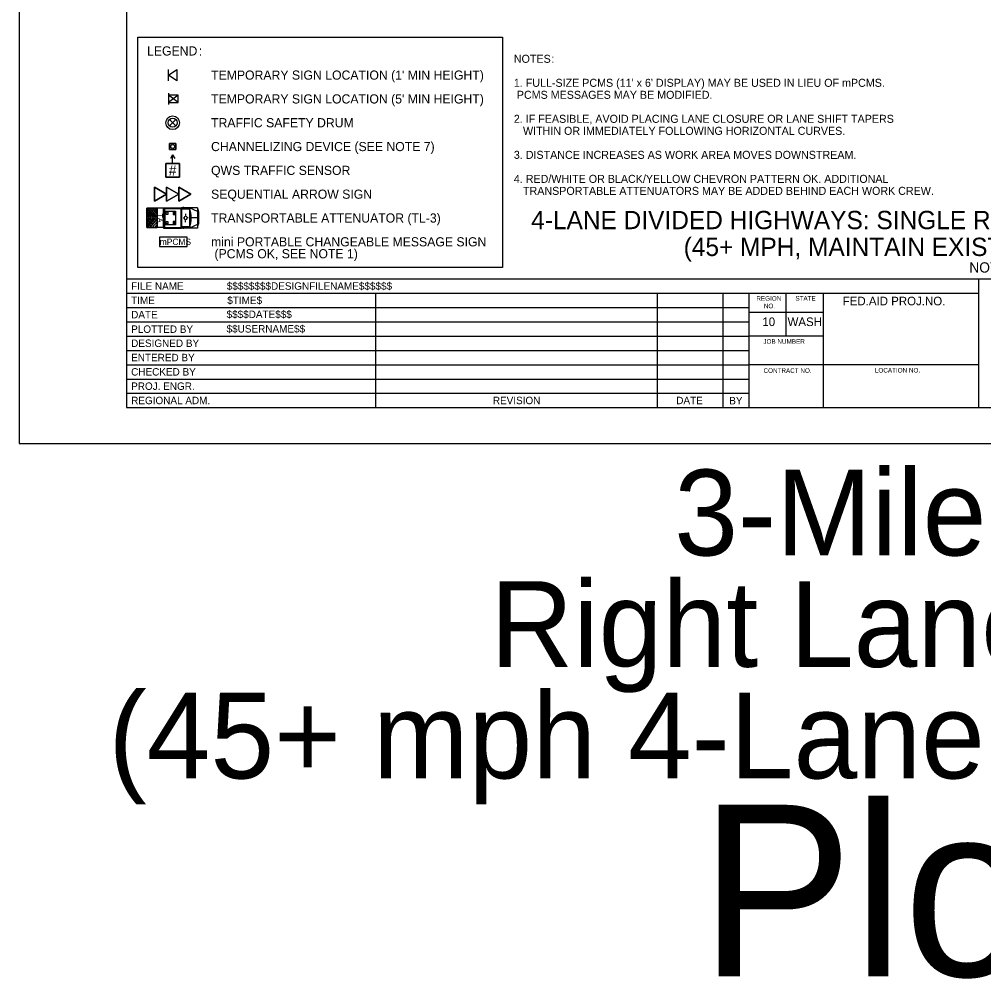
# Model space of a CAD drawing. Extents: x 99958 to 100136, y 99935 to 100013.
# Drawn here: x 100019.06 to 100027.5, y 99995.01 to 100003.4 of the extents above; entities that cross this region are included whole.
import ezdxf

# ---------------------------------------------------------------- set-up
doc = ezdxf.new("R2010")
doc.units = 0
for name, color, linetype in [('SH_DE_DetailHeading1Text', 7, 'Continuous'), ('SH_GI_GeneralNotesBodyText', 7, 'Continuous'), ('SH_GI_PlotLimits', 7, 'Continuous'), ('SH_GI_SheetBorder', 7, 'Continuous'), ('SH_GI_SheetLocationText', 7, 'Continuous'), ('SH_GI_SheetTextInCells', 7, 'Continuous'), ('SH_GI_TitleBlockText', 7, 'Continuous'), ('TR_WZ_PCMS', 7, 'Continuous'), ('TR_WZ_PortableSignMount5ftMinBlk-Wht', 7, 'Continuous'), ('TR_WZ_PortableSignMountBlk-Wht', 7, 'Continuous'), ('TR_WZ_SequentialArrowSign', 7, 'Continuous'), ('TR_WZ_TrafficCone', 7, 'Continuous'), ('TR_WZ_TrafficSafetyDrum', 7, 'Continuous'), ('TR_WZ_TransportableAttenuator', 7, 'Continuous'), ('TR_WZ_WorkZoneDetails', 7, 'Continuous'), ('TR_WZ_WorkZoneTextCurrent', 7, 'Continuous')]:
    doc.layers.add(name, color=color, linetype=linetype)

msp = doc.modelspace()

# ---------------------------------------------------------------- linework, layer by layer
at = {"layer": 'SH_GI_PlotLimits'}
msp.add_lwpolyline([(100019.0625, 99999.6875), (100036.0625, 99999.6875), (100036.0625, 100010.6875), (100019.0625, 100010.6875)], close=True, dxfattribs=at)
at = {"layer": 'SH_GI_SheetBorder'}
for p, q in [((100020, 100010.375), (100020, 100000)), ((100020, 100001.1259), (100035.75, 100001.1259)), ((100027.4566, 100000), (100027.4566, 100001.1259)), ((100020, 100001.0008), (100027.4566, 100001.0008)), ((100022.179, 100001.0008), (100022.179, 100000)), ((100024.641, 100001.0008), (100024.641, 100000)), ((100025.2164, 100001.0008), (100025.2164, 100000)), ((100025.4451, 100001.0008), (100025.4451, 100000)), ((100025.7719, 100000.6255), (100025.7719, 100001.0008)), ((100026.0956, 100000), (100026.0956, 100001.0008)), ((100020, 100000.8757), (100022.1821, 100000.8757)), ((100022.1821, 100000.8757), (100025.4466, 100000.8757)), ((100026.0958, 100000.831), (100025.4466, 100000.831)), ((100020, 100000.7506), (100022.1821, 100000.7506)), ((100022.1821, 100000.7506), (100025.4466, 100000.7506)), ((100020, 100000.6255), (100025.4466, 100000.6255)), ((100026.0958, 100000.6255), (100025.4466, 100000.6255)), ((100020, 100000.5004), (100025.4466, 100000.5004)), ((100020, 100000.3753), (100025.4466, 100000.3753)), ((100027.4566, 100000.3753), (100025.4466, 100000.3753)), ((100020, 100000.2502), (100025.4466, 100000.2502)), ((100020, 100000.1251), (100025.4466, 100000.1251)), ((100020, 100000), (100035.75, 100000))]:
    msp.add_line(p, q, dxfattribs=at)
at = {"layer": 'TR_WZ_PCMS'}
msp.add_lwpolyline([(100020.2899, 100001.41), (100020.5299, 100001.41), (100020.5299, 100001.49), (100020.2899, 100001.49)], close=True, dxfattribs=at)
msp.add_lwpolyline([(100020.2899, 100001.41), (100020.5299, 100001.41), (100020.5299, 100001.49), (100020.2899, 100001.49), (100020.2899, 100001.41)], dxfattribs=at)
at = {"layer": 'TR_WZ_PortableSignMount5ftMinBlk-Wht'}
for p, q in [((100020.3682, 100002.7497), (100020.3682, 100002.6497)), ((100020.4516, 100002.6672), (100020.3682, 100002.7322)), ((100020.4516, 100002.7322), (100020.3682, 100002.6672)), ((100020.4099, 100002.6997), (100020.4099, 100002.6997)), ((100020.41, 100002.6996), (100020.41, 100002.6996))]:
    msp.add_line(p, q, dxfattribs=at)
msp.add_lwpolyline([(100020.4516, 100002.6672), (100020.4516, 100002.7322), (100020.3682, 100002.7322), (100020.3682, 100002.6672)], close=True, dxfattribs=at)
at = {"layer": 'TR_WZ_PortableSignMountBlk-Wht'}
msp.add_line((100020.3682, 100002.858), (100020.3682, 100002.958), dxfattribs=at)
msp.add_lwpolyline([(100020.3682, 100002.9079), (100020.44, 100002.958), (100020.44, 100002.858)], close=True, dxfattribs=at)
at = {"layer": 'TR_WZ_SequentialArrowSign'}
for points in [[(100020.3508, 100001.8666), (100020.2441, 100001.8048), (100020.2441, 100001.9284), (100020.3508, 100001.8666)], [(100020.2441, 100001.9284), (100020.2441, 100001.8048), (100020.3508, 100001.8666), (100020.2441, 100001.9284)], [(100020.4575, 100001.8666), (100020.3508, 100001.8048), (100020.3508, 100001.8666), (100020.3508, 100001.9284), (100020.4575, 100001.8666)], [(100020.3508, 100001.9284), (100020.3508, 100001.8666), (100020.3508, 100001.8048), (100020.4575, 100001.8666), (100020.3508, 100001.9284)], [(100020.5641, 100001.8666), (100020.4575, 100001.8048), (100020.4575, 100001.8666), (100020.4575, 100001.9284), (100020.5641, 100001.8666)], [(100020.4575, 100001.9284), (100020.4575, 100001.8666), (100020.4575, 100001.8048), (100020.5641, 100001.8666), (100020.4575, 100001.9284)]]:
    msp.add_lwpolyline(points, dxfattribs=at)
at = {"layer": 'TR_WZ_TrafficCone'}
for points in [[(100020.4308, 100002.3098), (100020.4308, 100002.2565), (100020.3775, 100002.2565), (100020.3775, 100002.3098), (100020.4308, 100002.3098)], [(100020.3775, 100002.3098), (100020.3775, 100002.2565), (100020.4308, 100002.2565), (100020.4308, 100002.3098), (100020.3775, 100002.3098)]]:
    msp.add_lwpolyline(points, dxfattribs=at)
msp.add_circle((100020.4041, 100002.2832), 0.0167, dxfattribs=at)
at = {"layer": 'TR_WZ_TrafficSafetyDrum'}
for p, q in [((100020.4324, 100002.5197), (100020.3758, 100002.4632)), ((100020.4324, 100002.4632), (100020.3758, 100002.5197))]:
    msp.add_line(p, q, dxfattribs=at)
for radius in [0.06, 0.06, 0.04]:
    msp.add_circle((100020.4041, 100002.4914), radius, dxfattribs=at)
at = {"layer": 'TR_WZ_TransportableAttenuator'}
for p, q in [((100020.1791, 100001.7269), (100020.2355, 100001.659)), ((100020.1791, 100001.705), (100020.1791, 100001.7269)), ((100020.2355, 100001.659), (100020.1791, 100001.7269)), ((100020.1791, 100001.7269), (100020.1791, 100001.705)), ((100020.2551, 100001.6585), (100020.185, 100001.743)), ((100020.185, 100001.743), (100020.2041, 100001.743)), ((100020.185, 100001.743), (100020.2551, 100001.6585)), ((100020.2041, 100001.743), (100020.185, 100001.743)), ((100020.2041, 100001.743), (100020.2676, 100001.6659)), ((100020.2676, 100001.6659), (100020.2041, 100001.743)), ((100020.2676, 100001.6908), (100020.2248, 100001.743)), ((100020.2248, 100001.743), (100020.2439, 100001.743)), ((100020.2439, 100001.743), (100020.2248, 100001.743)), ((100020.2248, 100001.743), (100020.2676, 100001.6908)), ((100020.2439, 100001.743), (100020.2676, 100001.7144)), ((100020.2676, 100001.7144), (100020.2439, 100001.743)), ((100020.2676, 100001.574), (100020.2676, 100001.743)), ((100020.3279, 100001.743), (100020.2676, 100001.743)), ((100020.3208, 100001.7399), (100020.3208, 100001.5768)), ((100020.3241, 100001.7454), (100020.3274, 100001.7454)), ((100020.3274, 100001.7454), (100020.3274, 100001.5713)), ((100020.3279, 100001.7483), (100020.4803, 100001.7483)), ((100020.3279, 100001.7483), (100020.3279, 100001.5683)), ((100020.3279, 100001.7427), (100020.3279, 100001.574)), ((100020.3323, 100001.7411), (100020.3323, 100001.5755)), ((100020.3323, 100001.7411), (100020.476, 100001.7411)), ((100020.476, 100001.7411), (100020.476, 100001.5755)), ((100020.4803, 100001.7483), (100020.4803, 100001.5683)), ((100020.4824, 100001.7483), (100020.4824, 100001.5683)), ((100020.6223, 100001.7483), (100020.4824, 100001.7483)), ((100020.551, 100001.7344), (100020.4824, 100001.7344)), ((100020.5014, 100001.7509), (100020.493, 100001.7509)), ((100020.551, 100001.7483), (100020.5421, 100001.7344)), ((100020.551, 100001.7483), (100020.551, 100001.5683)), ((100020.5523, 100001.7483), (100020.5523, 100001.5683)), ((100020.6223, 100001.7153), (100020.5523, 100001.7483)), ((100020.6223, 100001.7483), (100020.6223, 100001.5683)), ((100020.6223, 100001.7483), (100020.6291, 100001.712)), ((100020.2174, 100001.6592), (100020.1791, 100001.705)), ((100020.1791, 100001.705), (100020.2174, 100001.6592)), ((100020.1791, 100001.6818), (100020.1987, 100001.6586)), ((100020.1791, 100001.635), (100020.1791, 100001.6818)), ((100020.1987, 100001.6586), (100020.1791, 100001.6818)), ((100020.1791, 100001.6818), (100020.1791, 100001.635)), ((100020.1791, 100001.6131), (100020.2174, 100001.6592)), ((100020.2174, 100001.6592), (100020.1791, 100001.6131)), ((100020.2355, 100001.659), (100020.1791, 100001.5911)), ((100020.1791, 100001.5911), (100020.2355, 100001.659)), ((100020.1987, 100001.6586), (100020.1791, 100001.635)), ((100020.1791, 100001.635), (100020.1987, 100001.6586)), ((100020.1849, 100001.5739), (100020.2551, 100001.6585)), ((100020.2551, 100001.6585), (100020.1849, 100001.5739)), ((100020.2676, 100001.6509), (100020.2037, 100001.5739)), ((100020.2037, 100001.5739), (100020.2676, 100001.6509)), ((100020.2676, 100001.7144), (100020.2676, 100001.6908)), ((100020.2676, 100001.6908), (100020.2676, 100001.7144)), ((100020.2676, 100001.6659), (100020.2676, 100001.6509)), ((100020.2676, 100001.6509), (100020.2676, 100001.6659)), ((100020.3208, 100001.671), (100020.3274, 100001.6676)), ((100020.3208, 100001.6456), (100020.3274, 100001.649)), ((100020.3226, 100001.6583), (100020.3257, 100001.6583)), ((100020.3241, 100001.6608), (100020.3241, 100001.6558)), ((100020.4951, 100001.6584), (100020.5045, 100001.6584)), ((100020.507, 100001.658), (100020.507, 100001.658)), ((100020.5175, 100001.694), (100020.5175, 100001.6794)), ((100020.5175, 100001.6226), (100020.5175, 100001.6372)), ((100020.5398, 100001.6584), (100020.5305, 100001.6584)), ((100020.6223, 100001.6583), (100020.566, 100001.6583)), ((100020.6291, 100001.712), (100020.6291, 100001.6047)), ((100020.1791, 100001.5911), (100020.1791, 100001.6131)), ((100020.1791, 100001.6131), (100020.1791, 100001.5911)), ((100020.2037, 100001.5739), (100020.1849, 100001.5739)), ((100020.1849, 100001.5739), (100020.2037, 100001.5739)), ((100020.2243, 100001.5739), (100020.2676, 100001.626)), ((100020.2676, 100001.626), (100020.2243, 100001.5739)), ((100020.2446, 100001.5739), (100020.2243, 100001.5739)), ((100020.2243, 100001.5739), (100020.2446, 100001.5739)), ((100020.2676, 100001.6011), (100020.2446, 100001.5739)), ((100020.2446, 100001.5739), (100020.2676, 100001.6011)), ((100020.2676, 100001.626), (100020.2676, 100001.6011)), ((100020.2676, 100001.6011), (100020.2676, 100001.626)), ((100020.3279, 100001.574), (100020.2676, 100001.574)), ((100020.3241, 100001.5713), (100020.3274, 100001.5713)), ((100020.3279, 100001.5683), (100020.4803, 100001.5683)), ((100020.3323, 100001.5755), (100020.476, 100001.5755)), ((100020.551, 100001.5823), (100020.4824, 100001.5823)), ((100020.6223, 100001.5683), (100020.4824, 100001.5683)), ((100020.5014, 100001.5658), (100020.493, 100001.5658)), ((100020.5437, 100001.5823), (100020.551, 100001.5683)), ((100020.6223, 100001.6013), (100020.5523, 100001.5683)), ((100020.6223, 100001.5683), (100020.6291, 100001.6047))]:
    msp.add_line(p, q, dxfattribs=at)
for points in [[(100020.2676, 100001.5739), (100020.1791, 100001.5739), (100020.1791, 100001.743), (100020.2676, 100001.743)], [(100020.3398, 100001.7183), (100020.4298, 100001.7183), (100020.4298, 100001.5983), (100020.3398, 100001.5983)], [(100020.3473, 100001.7108), (100020.3623, 100001.7108), (100020.3623, 100001.6883), (100020.3473, 100001.6883)], [(100020.4223, 100001.7108), (100020.4073, 100001.7108), (100020.4073, 100001.6883), (100020.4223, 100001.6883)], [(100020.3473, 100001.6283), (100020.3623, 100001.6283), (100020.3623, 100001.6058), (100020.3473, 100001.6058)], [(100020.4223, 100001.6283), (100020.4073, 100001.6283), (100020.4073, 100001.6058), (100020.4223, 100001.6058)]]:
    msp.add_lwpolyline(points, close=True, dxfattribs=at)
msp.add_lwpolyline([(100020.2676, 100001.743), (100020.1791, 100001.743), (100020.1791, 100001.5739), (100020.2676, 100001.574)], dxfattribs=at)
for centre, major_axis, start_param, end_param in [((100020.3241, 100001.7399), (0, 0.00549), 6.283185, 7.853982), ((100020.4523, 100001.6583), (0, 0.1889), 4.215852, 5.209111), ((100020.3241, 100001.5768), (0, -0.00549), 4.712389, 6.283185)]:
    msp.add_ellipse(centre, major_axis=major_axis, ratio=0.60201, start_param=start_param, end_param=end_param, dxfattribs=at)
for centre, major_axis in [((100020.3241, 100001.6583), (0, -0.00254)), ((100020.5175, 100001.6583), (0, -0.0173))]:
    msp.add_ellipse(centre, major_axis=major_axis, ratio=0.60201, dxfattribs=at)
at = {"layer": 'TR_WZ_WorkZoneDetails'}
for p, q in [((100020.4041, 100002.2099), (100020.3854, 100002.1774)), ((100020.4041, 100002.1349), (100020.4041, 100002.2099)), ((100020.4041, 100002.2099), (100020.4229, 100002.1774))]:
    msp.add_line(p, q, dxfattribs=at)
msp.add_lwpolyline([(100020.3441, 100002.1349), (100020.4641, 100002.1349), (100020.4641, 100002.0149), (100020.3441, 100002.0149)], close=True, dxfattribs=at)
msp.add_lwpolyline([(100020.3441, 100002.1349), (100020.3441, 100002.0149), (100020.4641, 100002.0149), (100020.4641, 100002.1349), (100020.4041, 100002.1349), (100020.3441, 100002.1349)], dxfattribs=at)
at = {"layer": 'TR_WZ_WorkZoneTextCurrent'}
msp.add_lwpolyline([(100020.1, 100003.2393), (100023.2886, 100003.2393), (100023.2886, 100001.2259), (100020.1, 100001.2259)], close=True, dxfattribs=at)

# ---------------------------------------------------------------- texts
at = {"layer": 'SH_DE_DetailHeading1Text'}
for s, height, p in [('4-LANE DIVIDED HIGHWAYS: SINGLE RIGHT LANE CLOSURE + 3-MILE QWS', 0.16, (100023.5403, 100001.5606)), ('(45+ MPH, MAINTAIN EXISTING SPEED LIMIT)', 0.16, (100024.8739, 100001.3259)), ('NOT TO SCALE', 0.09, (100027.3725, 100001.1809))]:
    msp.add_text(s, height=height, rotation=360, dxfattribs=at).set_placement(p)
at = {"layer": 'SH_GI_GeneralNotesBodyText'}
for s, p in [('NOTES', (100023.3886, 100003.0156)), (':', (100023.7161, 100003.0156)), ("1. FULL-SIZE PCMS (11' x 6' DISPLAY) MAY BE USED IN LIEU OF mPCMS.", (100023.3886, 100002.8056)), (' PCMS MESSAGES MAY BE MODIFIED.', (100023.3886, 100002.7006)), ('2. IF FEASIBLE, AVOID PLACING LANE CLOSURE OR LANE SHIFT TAPERS ', (100023.3886, 100002.4906)), ('WITHIN OR IMMEDIATELY FOLLOWING HORIZONTAL CURVES.', (100023.4686, 100002.3856)), ('3. DISTANCE INCREASES AS WORK AREA MOVES DOWNSTREAM.', (100023.3886, 100002.1756)), ('4. RED/WHITE OR BLACK/YELLOW CHEVRON PATTERN OK. ADDITIONAL ', (100023.3886, 100001.9656)), ('TRANSPORTABLE ATTENUATORS MAY BE ADDED BEHIND EACH WORK CREW.', (100023.4686, 100001.8606))]:
    msp.add_text(s, height=0.07, rotation=360, dxfattribs=at).set_placement(p)
at = {"layer": 'SH_GI_SheetLocationText'}
for s, height, p in [('3-Mile QWS', 0.75, (100024.7916, 99998.7071)), ('Right Lane Closure', 0.75, (100023.1834, 99997.7321)), ('(45+ mph 4-Lane Divided Hwys)', 0.75, (100019.8424, 99996.7571)), ('Plot 2', 1.5, (100025.015, 99995.0267))]:
    msp.add_text(s, height=height, dxfattribs=at).set_placement(p)
at = {"layer": 'SH_GI_SheetTextInCells'}
for s, height, p in [('FILE NAME', 0.06505, (100020.041, 100001.0308)), ('TIME', 0.06505, (100020.041, 100000.9057)), ('REGION', 0.04003, (100025.5099, 100000.9352)), ('STATE', 0.04003, (100025.8511, 100000.9357)), ('FED.AID PROJ.NO.', 0.07506, (100026.2652, 100000.8945)), ('NO.', 0.04003, (100025.5752, 100000.869)), ('DATE', 0.06505, (100020.041, 100000.7806)), ('PLOTTED BY', 0.06505, (100020.041, 100000.6538)), ('10', 0.07506, (100025.5621, 100000.7131)), ('WASH', 0.07506, (100025.7826, 100000.7131)), ('DESIGNED BY', 0.065052, (100020.041, 100000.5304)), ('JOB NUMBER', 0.04003, (100025.5712, 100000.5587)), ('ENTERED BY', 0.06505, (100020.041, 100000.4053)), ('CHECKED BY', 0.06505, (100020.041, 100000.2802)), ('CONTRACT NO.', 0.040032, (100025.5725, 100000.3037)), ('LOCATION NO.', 0.040032, (100026.5465, 100000.3067)), ('PROJ. ENGR.', 0.065052, (100020.041, 100000.1551)), ('REGIONAL ADM.', 0.065052, (100020.041, 100000.03)), ('REVISION', 0.06505, (100023.2048, 100000.03)), ('DATE', 0.06505, (100024.8091, 100000.03)), ('BY', 0.06505, (100025.2725, 100000.0285))]:
    msp.add_text(s, height=height, dxfattribs=at).set_placement(p)
at = {"layer": 'SH_GI_TitleBlockText'}
for s, height, p in [('$$$$$$$$DESIGNFILENAME$$$$$$', 0.065052, (100020.8775, 100001.0308)), ('$TIME$', 0.06505, (100020.882, 100000.9059)), ('$$$$DATE$$$', 0.065052, (100020.8759, 100000.7835)), ('$$USERNAME$$', 0.065052, (100020.8759, 100000.6567))]:
    msp.add_text(s, height=height, dxfattribs=at).set_placement(p)
at = {"layer": 'TR_WZ_PCMS'}
msp.add_text('mPCMS', height=0.055, rotation=360, dxfattribs=at).set_placement((100020.2914, 100001.4225))
at = {"layer": 'TR_WZ_TransportableAttenuator'}
msp.add_text('TA', height=0.045, rotation=269.99999, dxfattribs=at).set_placement((100020.2717, 100001.6978))
at = {"layer": 'TR_WZ_WorkZoneDetails'}
msp.add_text('#', height=0.09, dxfattribs=at).set_placement((100020.3702, 100002.0299))
at = {"layer": 'TR_WZ_WorkZoneTextCurrent'}
for s, p in [('LEGEND', (100020.18, 100003.0793)), (':', (100020.6328, 100003.0793)), ("TEMPORARY SIGN LOCATION (1' MIN HEIGHT)", (100020.74, 100002.868)), ("TEMPORARY SIGN LOCATION (5' MIN HEIGHT)", (100020.74, 100002.6597)), ('TRAFFIC SAFETY DRUM', (100020.74, 100002.4514)), ('CHANNELIZING DEVICE (SEE NOTE 7)', (100020.74, 100002.2432)), ('QWS TRAFFIC SENSOR', (100020.74, 100002.0349)), ('SEQUENTIAL ARROW SIGN', (100020.74, 100001.8266)), ('TRANSPORTABLE ATTENUATOR (TL-3)', (100020.74, 100001.6183)), ('mini PORTABLE CHANGEABLE MESSAGE SIGN', (100020.74, 100001.41)), (' (PCMS OK, SEE NOTE 1)', (100020.74, 100001.3059))]:
    msp.add_text(s, height=0.08, rotation=360, dxfattribs=at).set_placement(p)

doc.saveas('drawing.dxf')
